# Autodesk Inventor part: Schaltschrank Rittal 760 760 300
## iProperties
Created: 2010-08
Part Number: Schaltschrank Rittal 760 760 300
Document SubType Name: Modeling
Designer: Administrator
Density: 1 g/cm^3
Author: Administrator
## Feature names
1. Extrusion1
